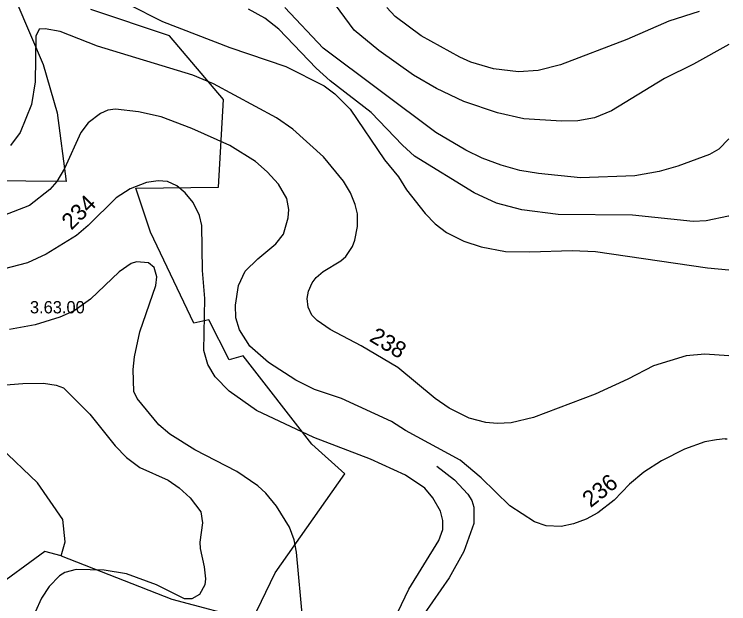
# Model space of a CAD drawing. Extents: x -662500 to -655523, y -1056000 to -1049993.
# Drawn here: x -659233.6 to -658797.7, y -1053226.8 to -1052866.9 of the extents above; entities that cross this region are included whole.
import ezdxf

# ---------------------------------------------------------------- set-up
doc = ezdxf.new("R2010")
doc.units = 0
doc.layers.add('Vrstva 24', color=7, linetype='Continuous')
doc.layers.add('Vrstva 7', color=7, linetype='Continuous')

msp = doc.modelspace()

# ---------------------------------------------------------------- linework, layer by layer
at = {"layer": 'Vrstva 24'}
for points in [[(-659232, -1052860), (-659216, -1052897.5), (-659207.5, -1052927), (-659202, -1052969), (-659251.5, -1052968.5), (-659287, -1052965.5), (-659289, -1052959), (-659374, -1052944)], [(-659205, -1053197.5), (-659137.5, -1053224), (-659088.5, -1053237), (-659074.5, -1053208), (-659032, -1053147.5), (-659052, -1053129.5), (-659094, -1053075.5), (-659102.5, -1053078), (-659115, -1053053.5), (-659124, -1053055.5), (-659150.5, -1053000), (-659159.5, -1052973), (-659109, -1052972.5), (-659106, -1052919), (-659139, -1052880), (-659187, -1052864)], [(-659205, -1053197.5), (-659202.5, -1053189), (-659204, -1053175.5), (-659219.5, -1053153), (-659242, -1053131.5), (-659292, -1053090), (-659334, -1053031.5), (-659353.19, -1053000), (-659366, -1052977.5), (-659374, -1052944)], [(-659205, -1053197.5), (-659215, -1053195), (-659248, -1053219), (-659247.5, -1053241.5), (-659244.5, -1053268.5), (-659251.5, -1053282), (-659251, -1053327), (-659256, -1053335), (-659251.5, -1053339.5), (-659244, -1053339.5)]]:
    msp.add_lwpolyline(points, dxfattribs=at)
at = {"layer": 'Vrstva 7'}
for p, q in [((-659164.15, -1052860.7), (-659143.22, -1052871.38)), ((-659026.19, -1052876.5), (-659037.72, -1052861.13)), ((-659080.86, -1052869.24), (-659090.83, -1052863.69)), ((-659045.27, -1052887.61), (-659068.61, -1052862.84)), ((-659001.27, -1052868.25), (-659006.25, -1052862.84)), ((-658815.75, -1052865.11), (-658834.26, -1052871.09)), ((-659072.32, -1052875.93), (-659080.86, -1052869.24)), ((-658985.46, -1052880.06), (-659001.27, -1052868.25)), ((-659143.22, -1052871.38), (-659102.22, -1052887.18)), ((-658834.26, -1052871.09), (-658859.89, -1052882.2)), ((-659218.54, -1052876.08), (-659220.54, -1052880.35)), ((-659214.7, -1052875.79), (-659218.54, -1052876.08)), ((-659205.59, -1052877.36), (-659214.7, -1052875.79)), ((-659182.81, -1052886.33), (-659205.59, -1052877.36)), ((-659049.54, -1052899.85), (-659072.32, -1052875.93)), ((-659011.24, -1052889.03), (-659026.19, -1052876.5)), ((-659220.54, -1052880.35), (-659220.96, -1052908.11)), ((-658961.83, -1052893.16), (-658985.46, -1052880.06)), ((-658859.89, -1052882.2), (-658900.32, -1052897.86)), ((-659124.71, -1052904.13), (-659182.81, -1052886.33)), ((-659102.22, -1052887.18), (-659068.05, -1052898.72)), ((-658976.35, -1052939.15), (-659045.27, -1052887.61)), ((-658797.74, -1052885.45), (-658819.16, -1052897.29)), ((-658990.02, -1052903.98), (-659011.24, -1052889.03)), ((-658954.99, -1052896.15), (-658961.83, -1052893.16)), ((-658941.33, -1052900.28), (-658954.99, -1052896.15)), ((-659068.05, -1052898.72), (-659044.55, -1052910.68)), ((-659040.99, -1052907.54), (-659049.54, -1052899.85)), ((-658925.95, -1052902.13), (-658941.33, -1052900.28)), ((-658900.32, -1052897.86), (-658913.99, -1052901.28)), ((-658819.16, -1052897.29), (-658836.82, -1052906.12)), ((-659112.18, -1052909.39), (-659124.71, -1052904.13)), ((-658976.07, -1052912.24), (-658990.02, -1052903.98)), ((-658913.99, -1052901.28), (-658925.95, -1052902.13)), ((-659220.96, -1052908.11), (-659223.1, -1052922.07)), ((-659073.74, -1052930.18), (-659112.18, -1052909.39)), ((-659015.79, -1052926.91), (-659040.99, -1052907.54)), ((-658836.82, -1052906.12), (-658869.28, -1052925.77)), ((-659044.55, -1052910.68), (-659038, -1052915.52)), ((-658959.27, -1052920.07), (-658976.07, -1052912.24)), ((-659038, -1052915.52), (-659028.75, -1052924.77)), ((-659223.1, -1052922.07), (-659230.08, -1052939.15)), ((-658938.76, -1052927.05), (-658959.27, -1052920.07)), ((-659176.54, -1052925.48), (-659181.1, -1052927.48)), ((-659171.98, -1052924.91), (-659176.54, -1052925.48)), ((-659157.75, -1052926.48), (-659171.98, -1052924.91)), ((-659144.08, -1052929.61), (-659157.75, -1052926.48)), ((-659028.75, -1052924.77), (-659007.82, -1052955.81)), ((-658869.28, -1052925.77), (-658879.53, -1052930.18)), ((-659181.1, -1052927.48), (-659188.64, -1052933.17)), ((-659125.28, -1052936.59), (-659144.08, -1052929.61)), ((-659063.63, -1052937.02), (-659073.74, -1052930.18)), ((-658996.85, -1052946.84), (-659015.79, -1052926.91)), ((-658922.82, -1052930.75), (-658938.76, -1052927.05)), ((-658899.75, -1052932.18), (-658922.82, -1052930.75)), ((-658879.53, -1052930.18), (-658889.79, -1052931.89)), ((-659188.64, -1052933.17), (-659193.06, -1052939.15)), ((-658889.79, -1052931.89), (-658899.75, -1052932.18)), ((-659230.08, -1052939.15), (-659235.91, -1052947.12)), ((-659193.06, -1052939.15), (-659203.02, -1052961.08)), ((-659102.22, -1052947.12), (-659125.28, -1052936.59)), ((-659044.98, -1052953.96), (-659063.63, -1052937.02)), ((-658958.13, -1052949.83), (-658976.35, -1052939.15)), ((-658797.74, -1052943.05), (-658803.79, -1052949.26)), ((-659086.56, -1052956.81), (-659102.22, -1052947.12)), ((-658989.45, -1052953.53), (-658996.85, -1052946.84)), ((-658948.16, -1052954.67), (-658958.13, -1052949.83)), ((-658809.48, -1052952.53), (-658828.85, -1052959.65)), ((-658803.79, -1052949.26), (-658809.48, -1052952.53)), ((-659079.44, -1052963.07), (-659086.56, -1052956.81)), ((-659032.73, -1052968.77), (-659044.98, -1052953.96)), ((-659007.82, -1052955.81), (-658999.28, -1052966.2)), ((-658953, -1052975.89), (-658989.45, -1052953.53)), ((-658936.49, -1052959.08), (-658948.16, -1052954.67)), ((-659203.02, -1052961.08), (-659207.58, -1052968.91)), ((-658925.1, -1052962.22), (-658936.49, -1052959.08)), ((-658828.85, -1052959.65), (-658840.24, -1052962.93)), ((-659072.46, -1052970.62), (-659079.44, -1052963.07)), ((-658913.7, -1052964.21), (-658925.1, -1052962.22)), ((-658888.08, -1052966.77), (-658913.7, -1052964.21)), ((-658855.04, -1052965.63), (-658888.08, -1052966.77)), ((-658840.24, -1052962.93), (-658855.04, -1052965.63)), ((-659207.58, -1052968.91), (-659211.85, -1052973.89)), ((-659152.91, -1052969.62), (-659162.87, -1052973.47)), ((-659145.79, -1052968.62), (-659152.91, -1052969.62)), ((-659140.09, -1052968.91), (-659145.79, -1052968.62)), ((-659134.4, -1052971.61), (-659140.09, -1052968.91)), ((-659028.46, -1052975.89), (-659032.73, -1052968.77)), ((-658999.28, -1052966.2), (-658994.29, -1052974.03)), ((-659211.85, -1052973.89), (-659224.38, -1052983.57)), ((-659162.87, -1052973.47), (-659171.41, -1052979.02)), ((-659129.41, -1052975.89), (-659134.4, -1052971.61)), ((-659067.33, -1052979.3), (-659072.46, -1052970.62)), ((-658994.29, -1052974.03), (-658982.9, -1052988.56)), ((-659171.41, -1052979.02), (-659188.5, -1052995.96)), ((-659124.43, -1052981.87), (-659129.41, -1052975.89)), ((-659025.62, -1052983.01), (-659028.46, -1052975.89)), ((-658939.33, -1052982.15), (-658953, -1052975.89)), ((-659120.58, -1052989.84), (-659124.43, -1052981.87)), ((-659066.2, -1052986.14), (-659067.33, -1052979.3)), ((-659024.33, -1052988.7), (-659025.62, -1052983.01)), ((-658923.96, -1052986.28), (-658939.33, -1052982.15)), ((-659224.38, -1052983.57), (-659240.61, -1052989.98)), ((-659066.48, -1052991.26), (-659066.2, -1052986.14)), ((-658901.74, -1052989.13), (-658923.96, -1052986.28)), ((-659119.16, -1052995.82), (-659120.58, -1052989.84)), ((-659069.47, -1053001.23), (-659066.48, -1052991.26)), ((-659024.33, -1052996.39), (-659024.33, -1052988.7)), ((-658982.9, -1052988.56), (-658976.78, -1052994.82)), ((-658856.47, -1052989.55), (-658901.74, -1052989.13)), ((-658819.45, -1052993.4), (-658856.47, -1052989.55)), ((-658797.81, -1052990.27), (-658811.48, -1052993.11)), ((-658797.74, -1052990.24), (-658797.81, -1052990.27)), ((-659188.5, -1052995.96), (-659195.62, -1053001.94)), ((-659118.88, -1053023.44), (-659119.16, -1052995.82)), ((-659025.76, -1053004.93), (-659024.33, -1052996.39)), ((-658976.78, -1052994.82), (-658969.95, -1053000.09)), ((-658811.48, -1052993.11), (-658819.45, -1052993.4)), ((-658969.95, -1053000.09), (-658959.27, -1053005.5)), ((-659195.62, -1053001.94), (-659214.13, -1053013.47)), ((-659074.03, -1053007.07), (-659069.47, -1053001.23)), ((-659027.18, -1053008.63), (-659025.76, -1053004.93)), ((-659085.13, -1053016.18), (-659074.03, -1053007.07)), ((-659031.31, -1053014.9), (-659027.18, -1053008.63)), ((-658959.27, -1053005.5), (-658948.73, -1053008.92)), ((-658948.73, -1053008.92), (-658933.92, -1053011.77)), ((-659214.13, -1053013.47), (-659225.52, -1053018.6)), ((-658933.92, -1053011.77), (-658919.12, -1053012.05)), ((-658919.12, -1053012.05), (-658893.2, -1053011.05)), ((-658893.2, -1053011.05), (-658878.96, -1053011.77)), ((-658878.96, -1053011.77), (-658810.62, -1053021.73)), ((-659159.17, -1053018.03), (-659162.3, -1053019.03)), ((-659151.77, -1053018.74), (-659159.17, -1053018.03)), ((-659092.82, -1053023.73), (-659085.13, -1053016.18)), ((-659045.27, -1053024.01), (-659034.3, -1053017.46)), ((-659034.3, -1053017.46), (-659031.31, -1053014.9)), ((-659225.52, -1053018.6), (-659240.33, -1053022.59)), ((-659162.3, -1053019.03), (-659169.56, -1053024.15)), ((-659148.35, -1053021.59), (-659151.77, -1053018.74)), ((-659146.64, -1053027.14), (-659148.35, -1053021.59)), ((-658810.62, -1053021.73), (-658797.74, -1053022.91)), ((-659169.56, -1053024.15), (-659187.08, -1053040.81)), ((-659117.31, -1053040.53), (-659118.88, -1053023.44)), ((-659096.81, -1053032.55), (-659092.82, -1053023.73)), ((-659049.54, -1053027.57), (-659045.27, -1053024.01)), ((-659147.35, -1053032.55), (-659146.64, -1053027.14)), ((-659054.09, -1053035.97), (-659051.96, -1053030.84)), ((-659051.96, -1053030.84), (-659049.54, -1053027.57)), ((-659157.03, -1053060.75), (-659147.35, -1053032.55)), ((-659098.66, -1053044.51), (-659096.81, -1053032.55)), ((-659054.95, -1053040.53), (-659054.09, -1053035.97)), ((-659187.08, -1053040.81), (-659197.04, -1053047.93)), ((-659118.02, -1053072.14), (-659117.31, -1053040.53)), ((-659098.37, -1053052.2), (-659098.66, -1053044.51)), ((-659054.38, -1053045.65), (-659054.95, -1053040.53)), ((-659197.04, -1053047.93), (-659205.87, -1053051.92)), ((-659052.1, -1053050.64), (-659054.38, -1053045.65)), ((-659205.87, -1053051.92), (-659220.96, -1053056.47)), ((-659096.24, -1053059.61), (-659098.37, -1053052.2)), ((-659048.82, -1053053.91), (-659052.1, -1053050.64)), ((-659220.96, -1053056.47), (-659236.62, -1053059.32)), ((-659040.99, -1053059.32), (-659048.82, -1053053.91)), ((-659160.31, -1053076.12), (-659157.03, -1053060.75)), ((-659089.97, -1053069.57), (-659096.24, -1053059.61)), ((-659021.91, -1053069.29), (-659040.99, -1053059.32)), ((-659078.58, -1053079.54), (-659089.97, -1053069.57)), ((-658999.7, -1053082.67), (-659021.91, -1053069.29)), ((-659115.6, -1053080.68), (-659118.02, -1053072.14)), ((-658812.33, -1053074.41), (-658823.72, -1053075.41)), ((-658797.74, -1053075.52), (-658812.33, -1053074.41)), ((-659161.16, -1053083.81), (-659160.31, -1053076.12)), ((-658823.72, -1053075.41), (-658843.65, -1053081.53)), ((-659111.04, -1053088.22), (-659115.6, -1053080.68)), ((-659061.78, -1053090.36), (-659078.58, -1053079.54)), ((-658976.92, -1053101.47), (-658999.7, -1053082.67)), ((-658843.65, -1053081.53), (-658859.32, -1053089.79)), ((-659160.74, -1053097.2), (-659161.16, -1053083.81)), ((-659259.69, -1053094.92), (-659228.37, -1053092.35)), ((-659228.37, -1053092.35), (-659215.84, -1053092.21)), ((-659215.84, -1053092.21), (-659208.15, -1053093.35)), ((-659102.5, -1053097.05), (-659111.04, -1053088.22)), ((-659050.39, -1053096.05), (-659061.78, -1053090.36)), ((-658859.32, -1053089.79), (-658879.25, -1053098.9)), ((-659208.15, -1053093.35), (-659203.59, -1053094.92)), ((-659203.59, -1053094.92), (-659187.5, -1053111.01)), ((-659034.02, -1053101.61), (-659050.39, -1053096.05)), ((-659158.74, -1053101.61), (-659160.74, -1053097.2)), ((-659085.84, -1053108.87), (-659102.5, -1053097.05)), ((-658879.25, -1053098.9), (-658916.84, -1053113.14)), ((-659145.5, -1053117.55), (-659158.74, -1053101.61)), ((-659003.39, -1053115.57), (-659034.02, -1053101.61)), ((-658968.38, -1053107.45), (-658976.92, -1053101.47)), ((-659050.96, -1053125.39), (-659085.84, -1053108.87)), ((-658956.14, -1053113.43), (-658968.38, -1053107.45)), ((-659187.5, -1053111.01), (-659172.13, -1053130.37)), ((-658945.88, -1053116.27), (-658956.14, -1053113.43)), ((-658916.84, -1053113.14), (-658930.51, -1053116.42)), ((-659138.81, -1053123.39), (-659145.5, -1053117.55)), ((-658994.86, -1053121.11), (-659003.39, -1053115.57)), ((-658939.05, -1053116.84), (-658945.88, -1053116.27)), ((-658930.51, -1053116.42), (-658939.05, -1053116.84)), ((-658961.55, -1053139.2), (-658994.86, -1053121.11)), ((-659123.57, -1053132.79), (-659138.81, -1053123.39)), ((-659016.22, -1053138.63), (-659050.96, -1053125.39)), ((-658805.17, -1053126.73), (-658812.33, -1053127.95)), ((-658799.85, -1053126.11), (-658805.17, -1053126.73)), ((-658799.85, -1053126.11), (-658798.72, -1053126.1)), ((-659172.13, -1053130.37), (-659165.15, -1053137.63)), ((-658812.33, -1053127.95), (-658824.72, -1053132.5)), ((-659097.95, -1053146.17), (-659123.57, -1053132.79)), ((-658824.72, -1053132.5), (-658838.81, -1053139.48)), ((-659165.15, -1053137.63), (-659157.03, -1053143.61)), ((-658995, -1053148.31), (-659016.22, -1053138.63)), ((-658948.73, -1053149.88), (-658961.55, -1053139.2)), ((-658838.81, -1053139.48), (-658849.63, -1053146.46)), ((-659157.03, -1053143.61), (-659139.81, -1053151.44)), ((-658975.78, -1053142.9), (-658965.1, -1053151.16)), ((-659085.13, -1053154.86), (-659097.95, -1053146.17)), ((-658983.19, -1053156.28), (-658995, -1053148.31)), ((-658849.63, -1053146.46), (-658858.32, -1053153.86)), ((-659139.81, -1053151.44), (-659132.97, -1053156)), ((-658965.1, -1053151.16), (-658956.99, -1053159.84)), ((-658931.22, -1053167.1), (-658948.73, -1053149.88)), ((-659132.97, -1053156), (-659126.42, -1053162.12)), ((-659080.15, -1053159.42), (-659085.13, -1053154.86)), ((-658978.2, -1053162.12), (-658983.19, -1053156.28)), ((-658858.32, -1053153.86), (-658867.72, -1053163.54)), ((-659126.42, -1053162.12), (-659119.73, -1053170.8)), ((-659073.6, -1053167.25), (-659080.15, -1053159.42)), ((-658973.65, -1053170.38), (-658978.2, -1053162.12)), ((-658956.99, -1053159.84), (-658954.57, -1053163.83)), ((-658954.57, -1053163.83), (-658953.29, -1053167.81)), ((-658867.72, -1053163.54), (-658877.54, -1053171.38)), ((-659119.73, -1053170.8), (-659118.88, -1053177.5)), ((-659065.62, -1053180.06), (-659073.6, -1053167.25)), ((-658972.22, -1053176.07), (-658973.65, -1053170.38)), ((-658953.29, -1053167.81), (-658953.29, -1053177.78)), ((-658916.27, -1053176.78), (-658931.22, -1053167.1)), ((-658884.66, -1053175.22), (-658892.35, -1053178.07)), ((-658877.54, -1053171.38), (-658884.66, -1053175.22)), ((-659118.88, -1053177.5), (-659120.44, -1053189.17)), ((-658972.08, -1053181.48), (-658972.22, -1053176.07)), ((-658953.29, -1053177.78), (-658959.27, -1053194.87)), ((-658909.11, -1053179.17), (-658916.27, -1053176.78)), ((-658900.04, -1053179.77), (-658909.11, -1053179.17)), ((-658892.35, -1053178.07), (-658900.04, -1053179.77)), ((-659062.78, -1053187.75), (-659065.62, -1053180.06)), ((-658974.64, -1053188.32), (-658972.08, -1053181.48)), ((-659061.35, -1053195.44), (-659062.78, -1053187.75)), ((-658993.01, -1053217.93), (-658974.64, -1053188.32)), ((-659120.44, -1053189.17), (-659120.3, -1053193.16)), ((-659120.3, -1053193.16), (-659117.74, -1053204.27)), ((-659054.8, -1053267.2), (-659061.35, -1053195.44)), ((-658959.27, -1053194.87), (-658968.38, -1053211.1)), ((-659117.74, -1053204.27), (-659116.88, -1053211.67)), ((-659206.01, -1053209.82), (-659212.42, -1053216.37)), ((-659202.74, -1053207.68), (-659206.01, -1053209.82)), ((-659195.9, -1053205.97), (-659202.74, -1053207.68)), ((-659178.82, -1053206.4), (-659195.9, -1053205.97)), ((-659165.15, -1053208.68), (-659178.82, -1053206.4)), ((-659146.78, -1053215.23), (-659165.15, -1053208.68)), ((-659116.88, -1053211.67), (-659117.31, -1053215.37)), ((-658968.38, -1053211.1), (-658983.61, -1053233.03)), ((-659212.42, -1053216.37), (-659217.12, -1053223.49)), ((-659129.7, -1053223.91), (-659146.78, -1053215.23)), ((-659117.31, -1053215.37), (-659120.73, -1053221.21)), ((-658999.56, -1053231.89), (-658993.01, -1053217.93)), ((-659120.73, -1053221.21), (-659125.28, -1053223.77)), ((-659217.12, -1053223.49), (-659220.82, -1053232.03)), ((-659125.28, -1053223.77), (-659129.7, -1053223.91))]:
    msp.add_line(p, q, dxfattribs=at)

# ---------------------------------------------------------------- texts
at = {"layer": 'Vrstva 24'}
msp.add_text('3.63.00', height=7.5, dxfattribs=at).set_placement((-659224.1, -1053049.53))
at = {"layer": 'Vrstva 7'}
for s, rotation, p in [('234', 44.7609, (-659198.76, -1052999.09)), ('238', 328.9275, (-659017.57, -1053066.07)), ('236', 38.5594, (-658881.99, -1053168.53))]:
    msp.add_text(s, height=10, rotation=rotation, dxfattribs=at).set_placement(p)

doc.saveas('drawing.dxf')
